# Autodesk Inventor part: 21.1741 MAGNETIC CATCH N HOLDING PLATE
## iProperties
Created: 2007-03
Part Number: 21.1741 MAGNETIC CATCH N HOLDING PLATE
Document SubType Name: Modeling
Designer: Andy Moles
Material: Steel
Mass: 4.66127 g
Surface Area: 6.58008 cm^2
Volume: 0.593792 cm^3
Density: 7.85 g/cm^3
Author: Andy Moles
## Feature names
1. Extrusion1
2. Base1
